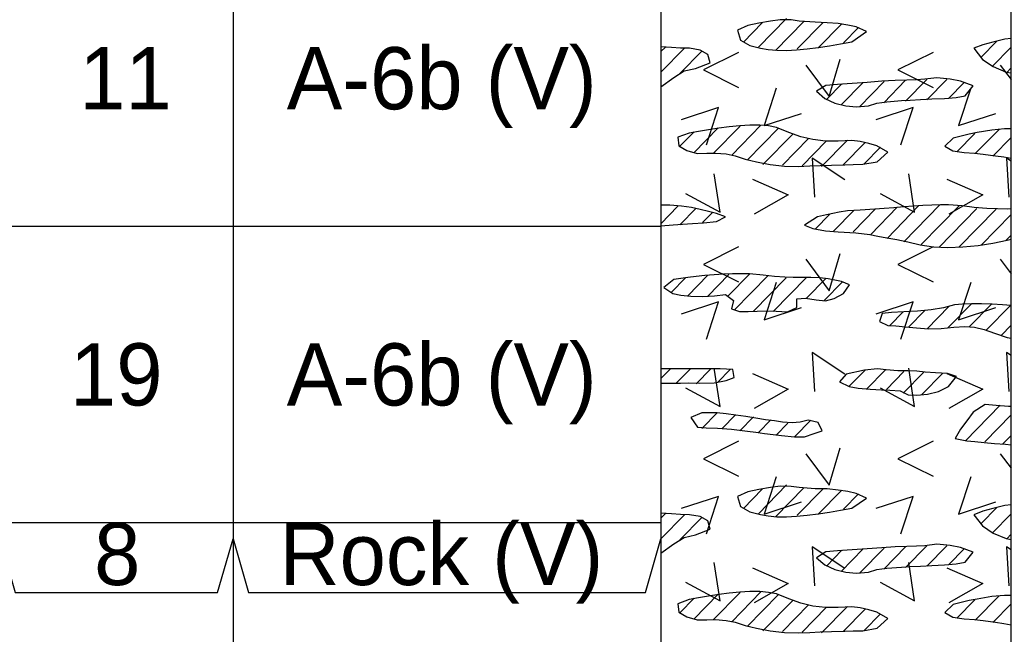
# Model space of a CAD drawing. Extents: x 0 to 0.833, y -0.323 to 0.608.
# Drawn here: x 0.7272 to 0.8333, y 0.0833 to 0.1491 of the extents above; entities that cross this region are included whole.
import ezdxf

# ---------------------------------------------------------------- set-up
doc = ezdxf.new("R2010")
doc.units = 0

msp = doc.modelspace()

# ---------------------------------------------------------------- linework, layer by layer
for points in [[(0, -0.32328), (0.83333, -0.32328), (0.83333, 0.60833), (0, 0.60833)], [(0.81233, 0.14887), (0.81063, 0.14899), (0.80977, 0.14912), (0.8086, 0.14913), (0.80755, 0.14899), (0.80632, 0.14879), (0.80513, 0.14854), (0.80403, 0.14802), (0.80436, 0.14696), (0.80536, 0.1464), (0.80647, 0.1461), (0.8073, 0.14595), (0.80824, 0.14587), (0.80926, 0.14586), (0.81035, 0.14591), (0.81149, 0.14601), (0.81267, 0.14616), (0.81386, 0.14635), (0.81506, 0.14656), (0.81625, 0.14679), (0.81783, 0.14787), (0.81673, 0.14837), (0.81585, 0.14858), (0.8148, 0.14873), (0.81361, 0.14883)], [(0.83265, 0.14706), (0.83136, 0.14675), (0.83028, 0.14647), (0.82934, 0.14608), (0.83026, 0.14488), (0.83142, 0.14412), (0.83279, 0.14354), (0.83333, 0.14344), (0.83333, 0.14715)], [(0.79583, 0.14196), (0.79719, 0.14295), (0.79831, 0.14365), (0.79951, 0.14393), (0.80111, 0.14453), (0.80086, 0.14541), (0.80002, 0.14589), (0.79889, 0.14608), (0.79791, 0.14611), (0.79694, 0.14617), (0.79583, 0.14625)], [(0.82537, 0.14291), (0.82408, 0.14276), (0.82319, 0.1427), (0.82214, 0.14267), (0.82091, 0.14264), (0.81947, 0.14255), (0.81792, 0.14243), (0.81632, 0.14231), (0.81475, 0.14221), (0.81348, 0.14211), (0.81247, 0.14147), (0.81337, 0.14071), (0.81444, 0.14021), (0.81561, 0.13992), (0.81675, 0.13981), (0.81807, 0.13993), (0.81896, 0.1402), (0.82003, 0.14035), (0.82157, 0.14047), (0.82253, 0.14053), (0.82362, 0.14058), (0.82483, 0.14065), (0.82618, 0.14071), (0.82745, 0.14082), (0.82842, 0.141), (0.82927, 0.14205), (0.82791, 0.14257), (0.82679, 0.14277)], [(0.79885, 0.137), (0.79763, 0.13654), (0.79773, 0.13564), (0.79859, 0.13512), (0.7997, 0.13482), (0.80074, 0.13483), (0.80165, 0.13484), (0.80281, 0.13476), (0.80377, 0.13455), (0.80486, 0.1342), (0.80606, 0.13391), (0.80751, 0.13363), (0.80905, 0.13345), (0.81052, 0.13342), (0.81177, 0.13347), (0.81289, 0.13352), (0.81408, 0.13355), (0.81553, 0.13359), (0.81642, 0.13362), (0.81745, 0.13365), (0.81897, 0.13392), (0.82011, 0.13496), (0.81896, 0.13563), (0.8181, 0.13589), (0.81717, 0.13609), (0.81626, 0.1362), (0.81479, 0.13614), (0.81343, 0.13614), (0.8121, 0.13629), (0.8108, 0.13659), (0.80953, 0.13705), (0.8082, 0.1376), (0.80736, 0.13776), (0.8064, 0.13784), (0.80536, 0.13784), (0.80427, 0.13778), (0.80314, 0.13767), (0.80201, 0.13752), (0.8009, 0.13735), (0.79984, 0.13718)], [(0.83263, 0.13744), (0.83126, 0.13731), (0.82969, 0.13704), (0.82883, 0.13687), (0.82712, 0.13646), (0.82623, 0.13559), (0.82708, 0.1351), (0.82831, 0.13491), (0.82941, 0.13484), (0.83033, 0.13475), (0.83165, 0.13457), (0.83253, 0.13443), (0.83333, 0.13429), (0.83333, 0.13744)], [(0.79583, 0.12704), (0.79715, 0.12715), (0.79814, 0.12722), (0.79922, 0.1273), (0.80039, 0.12739), (0.80179, 0.12751), (0.80275, 0.12802), (0.80179, 0.12836), (0.80091, 0.12858), (0.80003, 0.1288), (0.79909, 0.12901), (0.79803, 0.12917), (0.79677, 0.12927), (0.79583, 0.12925)], [(0.82816, 0.12479), (0.82978, 0.12496), (0.83137, 0.12521), (0.8329, 0.12552), (0.83333, 0.12563), (0.83333, 0.12887), (0.83295, 0.12884), (0.83188, 0.12886), (0.83071, 0.12891), (0.82938, 0.12901), (0.82807, 0.12918), (0.82662, 0.1293), (0.82576, 0.1293), (0.82484, 0.12928), (0.82387, 0.12923), (0.82286, 0.12916), (0.82182, 0.12908), (0.82077, 0.12899), (0.81973, 0.12891), (0.81872, 0.12884), (0.81715, 0.12874), (0.81579, 0.12865), (0.81491, 0.12852), (0.81357, 0.12824), (0.8126, 0.12803), (0.81121, 0.12711), (0.8121, 0.12675), (0.81345, 0.1265), (0.81479, 0.12641), (0.81668, 0.12631), (0.81818, 0.12611), (0.81905, 0.12596), (0.82, 0.12578), (0.82107, 0.12557), (0.82225, 0.12532), (0.82357, 0.12503), (0.82501, 0.1248), (0.82656, 0.12473)], [(0.79708, 0.11981), (0.79794, 0.11963), (0.79904, 0.11952), (0.80028, 0.11949), (0.80156, 0.11954), (0.80274, 0.1197), (0.80361, 0.11903), (0.80338, 0.11814), (0.80422, 0.11787), (0.80517, 0.11785), (0.80613, 0.1179), (0.8072, 0.11793), (0.80818, 0.1179), (0.80939, 0.11783), (0.81037, 0.1183), (0.81038, 0.11924), (0.8113, 0.11931), (0.81244, 0.11912), (0.81346, 0.11901), (0.81438, 0.11927), (0.81539, 0.11981), (0.81601, 0.12072), (0.81517, 0.1211), (0.81374, 0.12137), (0.81285, 0.12146), (0.81187, 0.12152), (0.81, 0.12152), (0.8091, 0.12154), (0.808, 0.12162), (0.80678, 0.12177), (0.8053, 0.1219), (0.80443, 0.12192), (0.80349, 0.1219), (0.80251, 0.12186), (0.80152, 0.1218), (0.80054, 0.12172), (0.79959, 0.12163), (0.7987, 0.12153), (0.79722, 0.12131), (0.79614, 0.12043)], [(0.83241, 0.11859), (0.83129, 0.11866), (0.83017, 0.11869), (0.8291, 0.1187), (0.82811, 0.11866), (0.82728, 0.11857), (0.82608, 0.11827), (0.82476, 0.11804), (0.8233, 0.11791), (0.82183, 0.11782), (0.82051, 0.11776), (0.81951, 0.11767), (0.81922, 0.1168), (0.82013, 0.11638), (0.82097, 0.11633), (0.822, 0.11623), (0.82318, 0.1161), (0.82448, 0.11601), (0.82584, 0.11604), (0.82719, 0.1162), (0.82836, 0.11627), (0.8294, 0.11619), (0.83043, 0.11595), (0.83156, 0.11556), (0.83291, 0.11507), (0.83333, 0.115), (0.83333, 0.11852)], [(0.79583, 0.11018), (0.79676, 0.11017), (0.79792, 0.11019), (0.79882, 0.11023), (0.79992, 0.11018), (0.80151, 0.11023), (0.80282, 0.11048), (0.80367, 0.1108), (0.80354, 0.11164), (0.80216, 0.11173), (0.79583, 0.11173)], [(0.81822, 0.10953), (0.81944, 0.10948), (0.82033, 0.10943), (0.82145, 0.10937), (0.82229, 0.10895), (0.82324, 0.10891), (0.82438, 0.10901), (0.82555, 0.1093), (0.82662, 0.10981), (0.82749, 0.1109), (0.82651, 0.11121), (0.82524, 0.11131), (0.82413, 0.11137), (0.82324, 0.11148), (0.82226, 0.1115), (0.82121, 0.11152), (0.81995, 0.11161), (0.81902, 0.11173), (0.81761, 0.11159), (0.81566, 0.11114), (0.81496, 0.11031), (0.81598, 0.10982), (0.81695, 0.10964)], [(0.83305, 0.10768), (0.83171, 0.10779), (0.83054, 0.10789), (0.82925, 0.10707), (0.82857, 0.10616), (0.82792, 0.10527), (0.82735, 0.10425), (0.82858, 0.10402), (0.82945, 0.10392), (0.83045, 0.10382), (0.83155, 0.10373), (0.83272, 0.10363), (0.83333, 0.10358), (0.83333, 0.10767)], [(0.80066, 0.10538), (0.80188, 0.10537), (0.80339, 0.10524), (0.80423, 0.10515), (0.8051, 0.10504), (0.806, 0.10492), (0.80692, 0.1048), (0.80784, 0.10468), (0.80875, 0.10457), (0.81014, 0.10443), (0.81119, 0.10444), (0.81222, 0.10478), (0.81308, 0.10507), (0.81267, 0.10597), (0.8116, 0.10622), (0.81075, 0.10602), (0.80989, 0.10594), (0.80885, 0.10602), (0.80799, 0.10613), (0.80703, 0.10627), (0.806, 0.10644), (0.80492, 0.1066), (0.80384, 0.10676), (0.8028, 0.10689), (0.80182, 0.10699), (0.8002, 0.10699), (0.79901, 0.10652), (0.79974, 0.10548)], [(0.81233, 0.09887), (0.81063, 0.09899), (0.80977, 0.09912), (0.8086, 0.09913), (0.80755, 0.09899), (0.80632, 0.09879), (0.80513, 0.09854), (0.80403, 0.09802), (0.80436, 0.09696), (0.80536, 0.0964), (0.80647, 0.0961), (0.8073, 0.09595), (0.80824, 0.09587), (0.80926, 0.09586), (0.81035, 0.09591), (0.81149, 0.09602), (0.81267, 0.09616), (0.81386, 0.09635), (0.81506, 0.09656), (0.81625, 0.09679), (0.81783, 0.09787), (0.81673, 0.09837), (0.81585, 0.09858), (0.8148, 0.09873), (0.81361, 0.09884)], [(0.83265, 0.09706), (0.83136, 0.09675), (0.83028, 0.09647), (0.82934, 0.09608), (0.83026, 0.09488), (0.83142, 0.09412), (0.83279, 0.09354), (0.83333, 0.09344), (0.83333, 0.09715)], [(0.79583, 0.09196), (0.79719, 0.09295), (0.79831, 0.09365), (0.79951, 0.09393), (0.80111, 0.09453), (0.80086, 0.09541), (0.80002, 0.09589), (0.79889, 0.09608), (0.79791, 0.09611), (0.79694, 0.09617), (0.79583, 0.09625)], [(0.82537, 0.09291), (0.82408, 0.09276), (0.82319, 0.0927), (0.82214, 0.09267), (0.82091, 0.09264), (0.81947, 0.09255), (0.81792, 0.09243), (0.81632, 0.09231), (0.81475, 0.09221), (0.81348, 0.09211), (0.81247, 0.09147), (0.81337, 0.09071), (0.81444, 0.09021), (0.81561, 0.08992), (0.81675, 0.08981), (0.81807, 0.08993), (0.81896, 0.0902), (0.82003, 0.09035), (0.82157, 0.09047), (0.82253, 0.09053), (0.82362, 0.09058), (0.82483, 0.09065), (0.82618, 0.09071), (0.82745, 0.09082), (0.82842, 0.091), (0.82927, 0.09205), (0.82791, 0.09257), (0.82679, 0.09277)], [(0.79885, 0.087), (0.79763, 0.08654), (0.79773, 0.08564), (0.79859, 0.08512), (0.7997, 0.08482), (0.80074, 0.08483), (0.80165, 0.08484), (0.80281, 0.08476), (0.80377, 0.08455), (0.80486, 0.0842), (0.80606, 0.08391), (0.80751, 0.08363), (0.80905, 0.08345), (0.81052, 0.08342), (0.81177, 0.08347), (0.81289, 0.08352), (0.81408, 0.08355), (0.81553, 0.08359), (0.81642, 0.08362), (0.81745, 0.08365), (0.81897, 0.08392), (0.82011, 0.08496), (0.81896, 0.08563), (0.8181, 0.08589), (0.81717, 0.08609), (0.81626, 0.0862), (0.81479, 0.08614), (0.81343, 0.08614), (0.8121, 0.08629), (0.8108, 0.08659), (0.80953, 0.08705), (0.8082, 0.0876), (0.80736, 0.08776), (0.8064, 0.08784), (0.80536, 0.08784), (0.80427, 0.08778), (0.80314, 0.08767), (0.80201, 0.08752), (0.8009, 0.08735), (0.79984, 0.08718)], [(0.83263, 0.08744), (0.83126, 0.08731), (0.82969, 0.08704), (0.82883, 0.08687), (0.82712, 0.08646), (0.82623, 0.08559), (0.82708, 0.0851), (0.82831, 0.08491), (0.82941, 0.08484), (0.83033, 0.08476), (0.83165, 0.08457), (0.83253, 0.08443), (0.83333, 0.08429), (0.83333, 0.08744)]]:
    msp.add_lwpolyline(points, close=True)
for points in [[(0.75, 0.55417), (0.75, -0.28575)], [(0.75, 0.55417), (0.75, -0.28575)], [(0.79583, 0.55417), (0.79583, -0.28575)], [(0.83333, -0.28575), (0.83333, 0.50165)], [(0.80465, 0.14675), (0.80667, 0.14883)], [(0.80626, 0.14619), (0.80928, 0.14928)], [(0.80809, 0.14585), (0.81111, 0.14895)], [(0.81041, 0.14602), (0.81318, 0.14885)], [(0.81264, 0.14609), (0.81518, 0.14869)], [(0.81536, 0.14667), (0.81699, 0.14833)], [(0.8301, 0.14509), (0.83184, 0.14688)], [(0.7963, 0.14621), (0.79583, 0.14573)], [(0.79834, 0.14608), (0.79583, 0.14351)], [(0.79786, 0.14338), (0.80023, 0.14581)], [(0.80412, 0.14563), (0.80038, 0.14376), (0.80412, 0.14188)], [(0.82496, 0.14563), (0.82121, 0.14376), (0.82496, 0.14188)], [(0.83131, 0.14412), (0.83333, 0.14619)], [(0.81134, 0.14429), (0.81384, 0.14092), (0.81503, 0.14492)], [(0.83217, 0.14429), (0.83333, 0.14273)], [(0.83285, 0.14349), (0.83333, 0.14398)], [(0.81519, 0.14228), (0.81354, 0.14058)], [(0.81514, 0.14001), (0.81748, 0.14241)], [(0.81709, 0.1398), (0.81974, 0.14251)], [(0.8197, 0.14025), (0.82203, 0.14265)], [(0.82202, 0.14042), (0.8243, 0.14275)], [(0.82431, 0.14055), (0.82644, 0.14274)], [(0.82663, 0.14071), (0.82834, 0.14247)], [(0.80818, 0.1418), (0.80687, 0.1378), (0.81087, 0.13911)], [(0.82901, 0.1418), (0.8277, 0.1378), (0.8317, 0.13911)], [(0.80069, 0.13572), (0.802, 0.13972), (0.798, 0.13841)], [(0.82152, 0.13572), (0.82284, 0.13972), (0.81884, 0.13841)], [(0.79938, 0.13713), (0.79786, 0.13558)], [(0.79933, 0.13487), (0.80195, 0.13756)], [(0.80142, 0.1348), (0.8043, 0.13775)], [(0.80653, 0.13783), (0.8034, 0.13461)], [(0.80506, 0.1341), (0.8084, 0.13753)], [(0.82751, 0.13498), (0.82945, 0.13696)], [(0.83203, 0.13739), (0.82949, 0.13479)], [(0.80997, 0.13693), (0.80675, 0.13362)], [(0.81164, 0.13642), (0.80884, 0.13356)], [(0.81353, 0.13614), (0.81094, 0.13349)], [(0.81303, 0.13342), (0.81579, 0.13625)], [(0.81534, 0.13358), (0.81768, 0.13597)], [(0.83138, 0.13452), (0.83333, 0.13652)], [(0.8176, 0.13368), (0.81934, 0.13547)], [(0.81551, 0.13199), (0.81201, 0.13431), (0.81226, 0.13012)], [(0.83333, 0.13398), (0.83284, 0.13431), (0.83309, 0.13012)], [(0.83333, 0.1343), (0.83333, 0.13431)], [(0.79847, 0.13051), (0.80215, 0.12851), (0.80153, 0.13264)], [(0.80562, 0.13206), (0.80946, 0.13037), (0.80581, 0.12831)], [(0.8193, 0.13051), (0.82299, 0.12851), (0.82236, 0.13264)], [(0.82645, 0.13206), (0.83029, 0.13037), (0.82664, 0.12831)], [(0.79765, 0.12915), (0.79583, 0.12728)], [(0.7996, 0.12894), (0.79786, 0.12716)], [(0.8143, 0.12648), (0.8165, 0.12873)], [(0.8164, 0.12641), (0.81879, 0.12886)], [(0.81829, 0.12613), (0.82114, 0.12905)], [(0.82004, 0.12571), (0.82346, 0.12922)], [(0.82569, 0.1293), (0.82184, 0.12535)], [(0.82775, 0.12919), (0.8237, 0.12505)], [(0.82964, 0.12892), (0.82557, 0.12474)], [(0.83173, 0.12885), (0.82774, 0.12476)], [(0.8013, 0.12846), (0.80027, 0.12741)], [(0.81392, 0.1283), (0.81235, 0.12669)], [(0.83333, 0.12827), (0.83012, 0.12498)], [(0.725, 0.127), (0.75, 0.127)], [(0.75, 0.127), (0.79583, 0.127)], [(0.83281, 0.12552), (0.83333, 0.12606)], [(0.80412, 0.1248), (0.80038, 0.12292), (0.80412, 0.12105)], [(0.82496, 0.1248), (0.82121, 0.12292), (0.82496, 0.12105)], [(0.81134, 0.12346), (0.81384, 0.12008), (0.81503, 0.12408)], [(0.83217, 0.12346), (0.83333, 0.1219)], [(0.79844, 0.12149), (0.79691, 0.11992)], [(0.79871, 0.11955), (0.80085, 0.12175)], [(0.80083, 0.11951), (0.80311, 0.12185)], [(0.80534, 0.12192), (0.80299, 0.11951)], [(0.80367, 0.118), (0.80732, 0.12174)], [(0.80571, 0.11788), (0.80924, 0.12149)], [(0.81142, 0.12151), (0.80785, 0.11786)], [(0.81141, 0.11929), (0.81348, 0.12141)], [(0.81528, 0.12105), (0.81331, 0.11903)], [(0.80818, 0.12097), (0.80687, 0.11697), (0.81087, 0.11828)], [(0.82901, 0.12097), (0.8277, 0.11697), (0.8317, 0.11828)], [(0.80069, 0.11489), (0.802, 0.11889), (0.798, 0.11757)], [(0.82152, 0.11489), (0.82284, 0.11889), (0.81884, 0.11757)], [(0.82233, 0.11619), (0.82408, 0.11798)], [(0.82433, 0.11602), (0.82666, 0.11841)], [(0.82909, 0.1187), (0.82656, 0.1161)], [(0.82885, 0.11623), (0.83122, 0.11866)], [(0.83325, 0.11852), (0.83065, 0.11586)], [(0.82035, 0.11637), (0.82176, 0.11782)], [(0.83333, 0.1164), (0.83227, 0.11531)], [(0.81551, 0.11116), (0.81201, 0.11347), (0.81226, 0.10928)], [(0.83333, 0.11315), (0.83284, 0.11347), (0.83309, 0.10928)], [(0.79583, 0.1107), (0.79681, 0.1117)], [(0.79898, 0.11172), (0.79747, 0.11017)], [(0.79847, 0.10968), (0.80215, 0.10768), (0.80153, 0.1118)], [(0.80116, 0.11173), (0.79959, 0.11013)], [(0.80328, 0.11169), (0.80188, 0.11026)], [(0.8177, 0.11159), (0.81596, 0.10981)], [(0.81988, 0.11161), (0.81785, 0.10953)], [(0.8193, 0.10968), (0.82299, 0.10768), (0.82236, 0.1118)], [(0.80562, 0.11122), (0.80946, 0.10954), (0.80581, 0.10748)], [(0.82185, 0.11142), (0.81997, 0.10949)], [(0.824, 0.11141), (0.82178, 0.10913)], [(0.82601, 0.11125), (0.82378, 0.10897)], [(0.82645, 0.11122), (0.83029, 0.10954), (0.82664, 0.10748)], [(0.83217, 0.10781), (0.82844, 0.10399)], [(0.80188, 0.10703), (0.8002, 0.10531)], [(0.8038, 0.10679), (0.80237, 0.10533)], [(0.80575, 0.10657), (0.80429, 0.10508)], [(0.80758, 0.10624), (0.80627, 0.10489)], [(0.81188, 0.10621), (0.81016, 0.10446)], [(0.83333, 0.10679), (0.83052, 0.10391)], [(0.80941, 0.1059), (0.80816, 0.10462)], [(0.83333, 0.10457), (0.83245, 0.10367)], [(0.80412, 0.10396), (0.80038, 0.10209), (0.80412, 0.10021)], [(0.81134, 0.10262), (0.81384, 0.09925), (0.81503, 0.10325)], [(0.82496, 0.10396), (0.82121, 0.10209), (0.82496, 0.10021)], [(0.83217, 0.10262), (0.83333, 0.10106)], [(0.80818, 0.10013), (0.80687, 0.09613), (0.81087, 0.09745)], [(0.82901, 0.10013), (0.8277, 0.09613), (0.8317, 0.09745)], [(0.80465, 0.09675), (0.80667, 0.09883)], [(0.80626, 0.09619), (0.80928, 0.09929)], [(0.80809, 0.09585), (0.81111, 0.09895)], [(0.81041, 0.09602), (0.81318, 0.09885)], [(0.80069, 0.09405), (0.802, 0.09805), (0.798, 0.09674)], [(0.81264, 0.0961), (0.81518, 0.0987)], [(0.81536, 0.09667), (0.81699, 0.09833)], [(0.82152, 0.09405), (0.82284, 0.09805), (0.81884, 0.09674)], [(0.8301, 0.09509), (0.83184, 0.09688)], [(0.7963, 0.09621), (0.79583, 0.09573)], [(0.79834, 0.09608), (0.79583, 0.09351)], [(0.79786, 0.09338), (0.80023, 0.09581)], [(0.83131, 0.09412), (0.83333, 0.09619)], [(0.725, 0.09525), (0.75, 0.09525)], [(0.75, 0.09525), (0.79583, 0.09525)], [(0.725, 0.09349), (0.72667, 0.08775), (0.74833, 0.08775), (0.75, 0.09349)], [(0.75, 0.09349), (0.75167, 0.08775), (0.79417, 0.08775), (0.79583, 0.09349)], [(0.83285, 0.09349), (0.83333, 0.09398)], [(0.81551, 0.09033), (0.81201, 0.09264), (0.81226, 0.08845)], [(0.81514, 0.09001), (0.81748, 0.09241)], [(0.81709, 0.0898), (0.81974, 0.09251)], [(0.8197, 0.09025), (0.82203, 0.09265)], [(0.82202, 0.09042), (0.8243, 0.09275)], [(0.82431, 0.09055), (0.82644, 0.09274)], [(0.82663, 0.09071), (0.82834, 0.09247)], [(0.83333, 0.09232), (0.83284, 0.09264), (0.83309, 0.08845)], [(0.81519, 0.09228), (0.81354, 0.09058)], [(0.79847, 0.08884), (0.80215, 0.08684), (0.80153, 0.09097)], [(0.80562, 0.09039), (0.80946, 0.08871), (0.80581, 0.08664)], [(0.8193, 0.08884), (0.82299, 0.08684), (0.82236, 0.09097)], [(0.82645, 0.09039), (0.83029, 0.08871), (0.82664, 0.08664)], [(0.79938, 0.08713), (0.79786, 0.08558)], [(0.79933, 0.08487), (0.80195, 0.08756)], [(0.80142, 0.0848), (0.8043, 0.08775)], [(0.80653, 0.08783), (0.8034, 0.08461)], [(0.80506, 0.0841), (0.8084, 0.08753)], [(0.83203, 0.08739), (0.82949, 0.08479)], [(0.80997, 0.08693), (0.80675, 0.08362)], [(0.81164, 0.08642), (0.80884, 0.08356)], [(0.81353, 0.08614), (0.81094, 0.08349)], [(0.81303, 0.08342), (0.81579, 0.08625)], [(0.82751, 0.08498), (0.82945, 0.08697)], [(0.83138, 0.08452), (0.83333, 0.08652)], [(0.81534, 0.08358), (0.81768, 0.08597)], [(0.8176, 0.08368), (0.81934, 0.08547)], [(0.83333, 0.0843), (0.83333, 0.08431)]]:
    msp.add_lwpolyline(points)

# ---------------------------------------------------------------- texts
for s, height, p in [('A-6b (V)', 0.006667, (0.75575, 0.13954)), ('11', 0.006667, (0.73352, 0.13954)), ('A-6b (V)', 0.006667, (0.75575, 0.10779)), ('19', 0.006667, (0.73253, 0.10779)), ('Rock (V)', 0.006667, (0.75497, 0.08854)), ('8', 0.00667, (0.73512, 0.08854))]:
    msp.add_text(s, height=height).set_placement(p)

doc.saveas('drawing.dxf')
